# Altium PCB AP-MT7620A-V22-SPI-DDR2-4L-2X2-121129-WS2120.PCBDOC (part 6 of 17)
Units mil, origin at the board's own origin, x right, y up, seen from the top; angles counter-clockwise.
Board outline 7316 x 4279 mil, 4 copper layers (Top, Inner Layer 2, Inner Layer 3, Bottom), stack 35.4 mil thick; 640 components, 473 nets, 2041 pads, 2358 vias.
Unrouted connection lines stored in the file: 11.
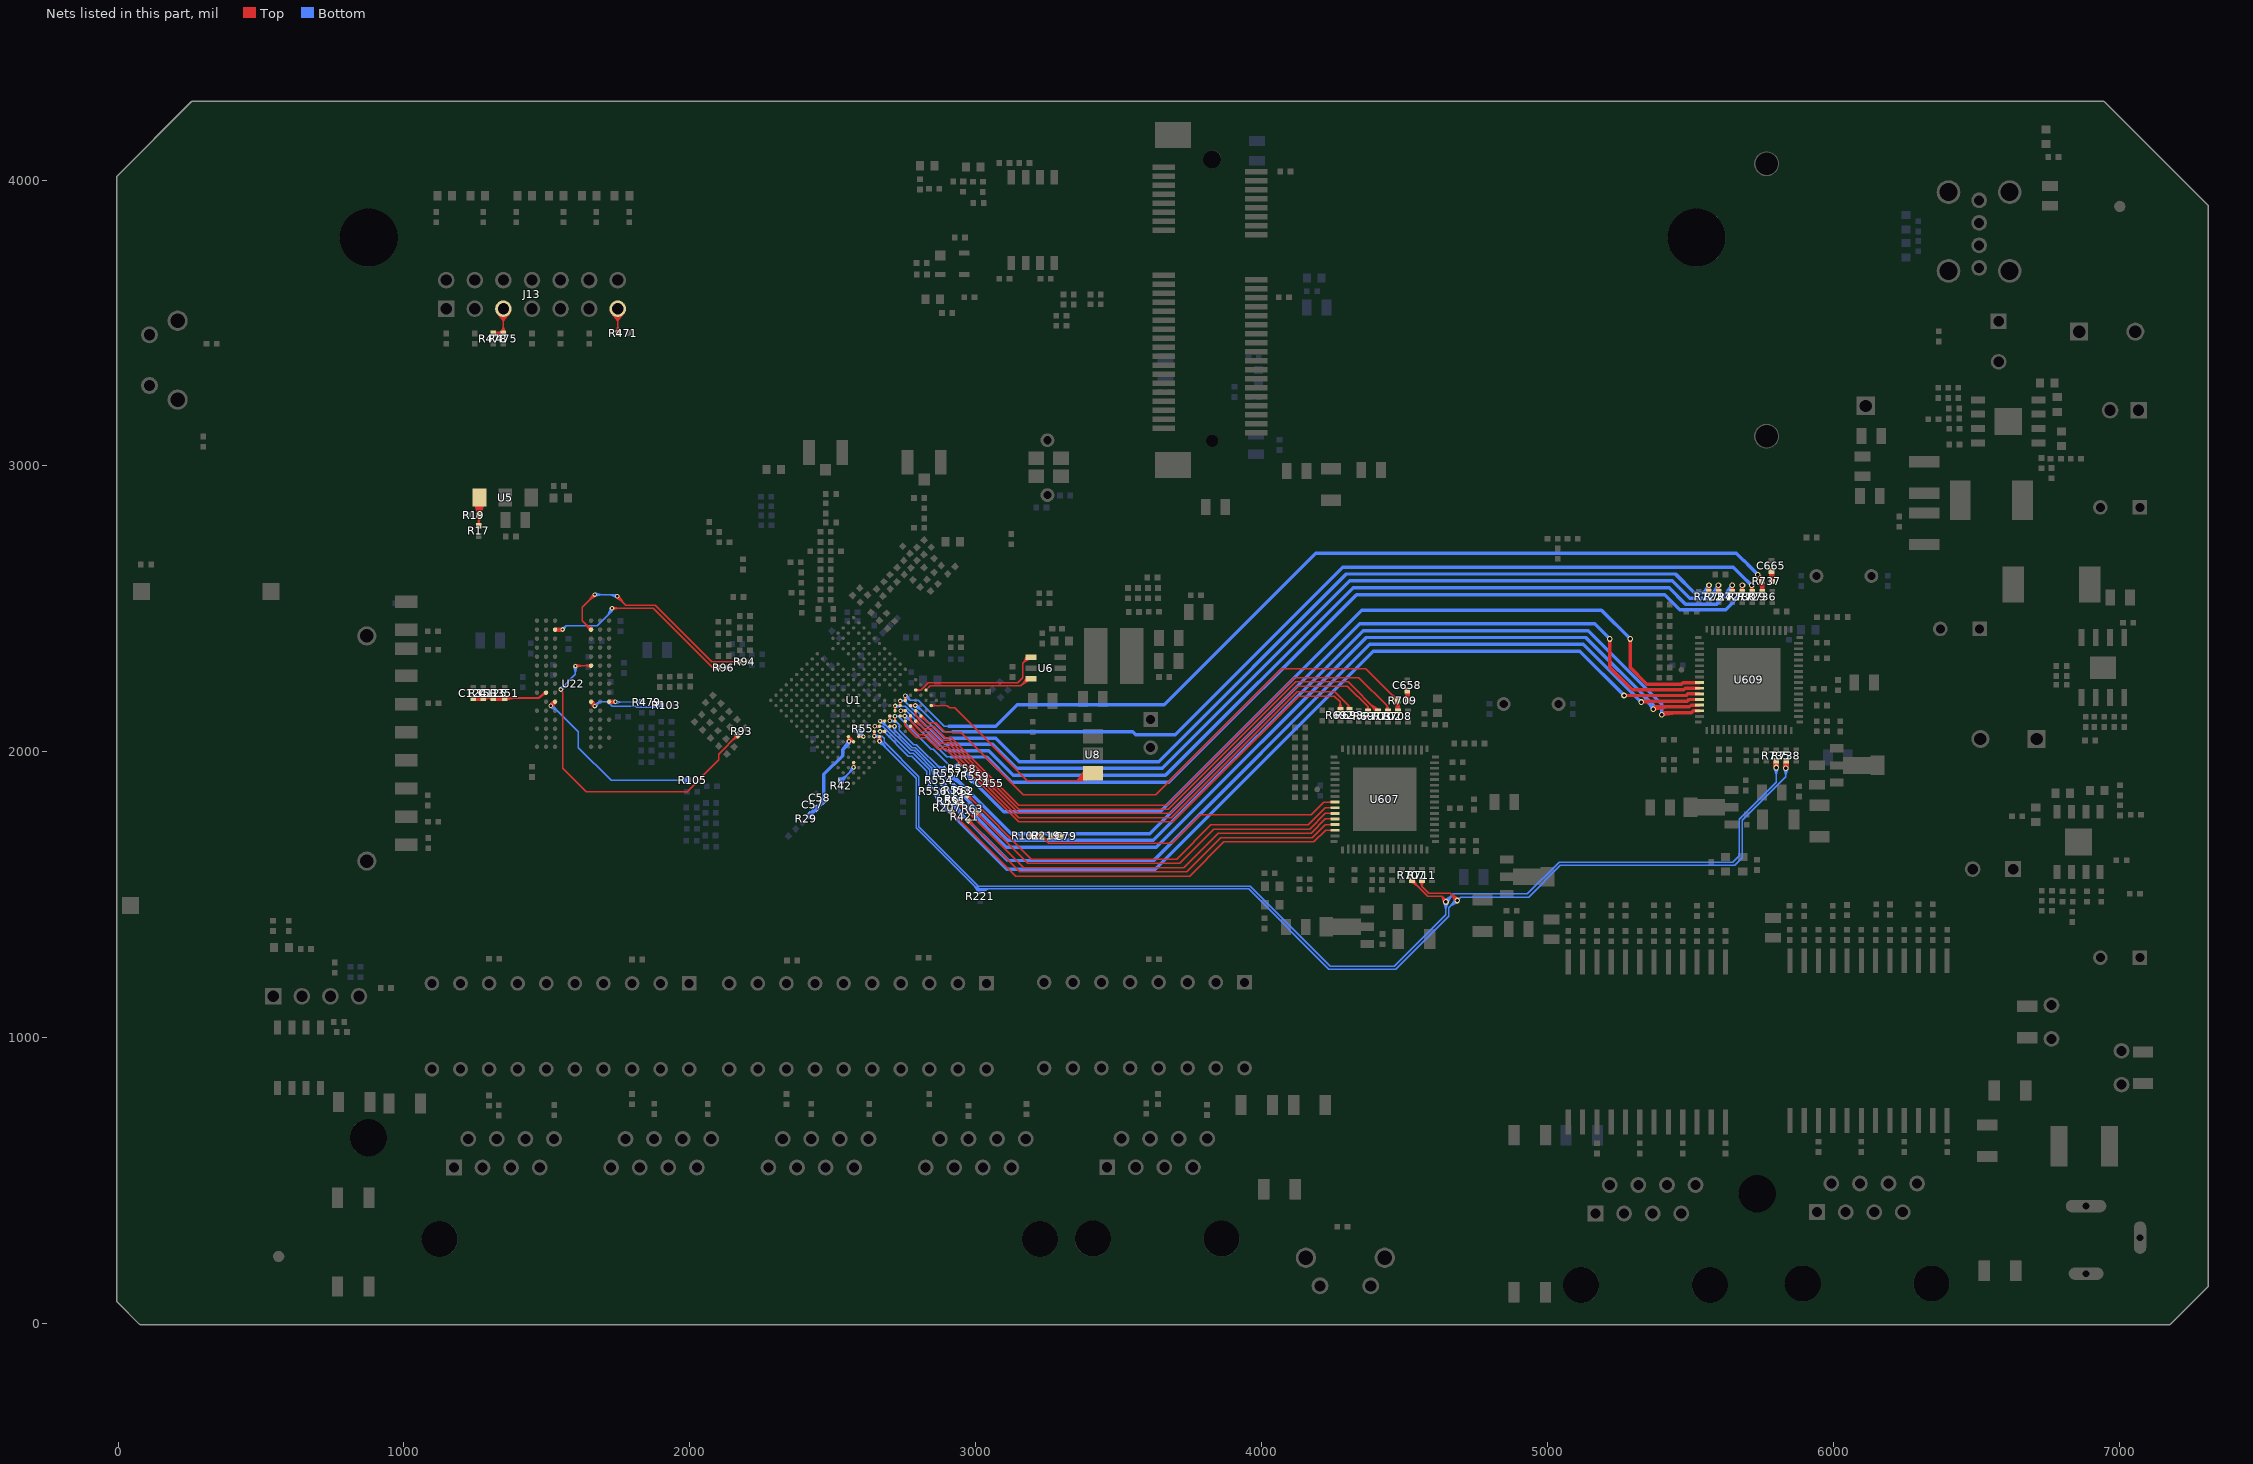
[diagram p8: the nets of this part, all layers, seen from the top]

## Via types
v1: diameter 20, hole 12, Top to Bottom, 2117 vias
v2: diameter 16, hole 8, Top to Bottom, 241 vias

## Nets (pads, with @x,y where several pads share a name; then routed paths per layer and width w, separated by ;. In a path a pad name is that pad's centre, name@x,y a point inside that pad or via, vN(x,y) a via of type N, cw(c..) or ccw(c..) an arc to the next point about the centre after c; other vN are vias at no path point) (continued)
DDR_MDQM1: R96.2 U22.B3 | length 1316
  Top w4.5: U22.B3@1529.12,2432.89 v2@1549.95,2428 ; U22.B3@1529.48,2421.75 v2@1549.95,2428 ; v2@1553,2433.39 U22.B3@1531.76,2422.44 ; v2@1553.28,2422.51 U22.B3@1531.65,2432.3 ; v2@1554.15,2433.69 U22.B3@1531.5,2427.39 ; v2@1554.3,2422.29 U22.B3@1531.5,2428 ; v2@1554.3,2433.71 U22.B3@1531.5,2428 ; v2@1554.44,2422.28 U22.B3@1531.5,2427.39 ; v2@1555.35,2433.74 U22.B3@1531.65,2432.3 ; v2@1555.66,2422.29 U22.B3@1531.76,2422.44 ; v2(1728,2502) 1873,2502 2080,2295 ; v2@1728.7,2496.29 1751.5,2502 v2@1728.7,2507.71 ; R96.2@2098.5,2287.4 2080,2295 ; R96.2@2098.5,2302.6 2080,2295 ; R96.2@2099.74,2291.76 2080,2295 ; R96.2@2099.74,2298.24 2080,2295 ; R96.2@2101,2295 R96.2@2100,2295 ; U22.B3@1531.5,2427.39 v2(1555,2428) ; U22.B3@1531.5,2428 v2(1555,2428) ; U22.B3@1531.65,2432.3 v2(1555,2428) ; U22.B3@1531.76,2422.44 v2(1555,2428) ; v2@1549.95,2428 U22.B3@1528.56,2427.3 1528.56,2428 v2(1555,2428) ; 2080,2295 R96.2@2100,2295 ; 2080,2295 R96.2@2100,2295
  Bottom w4.5: v2@1551.58,2432.63 1568.65,2441.65 ; v2(1555,2428) 1568.65,2441.65 ; v2@1559.63,2424.58 1568.65,2441.65 ; v2@1722.86,2504.59 1712.4,2477.4 ; v2@1732.53,2498.46 1712.4,2477.4 ; 1568.65,2441.65 1676.65,2441.65 1728,2493 v2(1728,2502) 1712.4,2477.4
DDR_MDQS0: R93.2 U22.F7 | length 1584.2
  Top w4.5: v2(1548.2,2218) 1556,2209 1556,1943 1638,1861 1991,1861 2102,1972 2102,1992.43 R93.2@2168.56,2058.99 ; v2@1600.38,2305.74 1623.56,2301.31 ; v2@1601.02,2294.34 1623.56,2301.31 ; U22.F7@1653.81,2295.74 1633.17,2301.31 ; U22.F7@1653.81,2306.89 1633.17,2301.31 ; R93.2@2162.25,2063.49 2151.94,2042.37 ; R93.2@2166.11,2061.12 2151.94,2042.37 ; R93.2@2169.27,2059.7 R93.2@2168.56,2058.99 ; R93.2@2170.69,2056.54 2151.94,2042.37 ; R93.2@2173.06,2052.68 2151.94,2042.37 ; 1623.56,2301.31 v2(1600,2300) 1600,2301.31 U22.F7@1654.55,2301.31 1633.17,2301.31 ; 2151.94,2042.37 R93.2@2168.56,2058.99
  Bottom w4.5: v2@1544.45,2222.35 1567.05,2238.05 ; v2@1552.78,2214.52 1567.05,2238.05 ; v2@1594.29,2299.3 1600,2276.5 ; v2@1605.71,2299.3 1600,2276.5 ; 1567.05,2238.05 v2(1548.2,2218) 1548.6,2218.4 1548.6,2219.6 1600,2271 v2(1600,2300) 1600,2276.5
DDR_MDQS1: R94.2 U22.B7 | length 1216.7
  Top w4.5: U22.B7@1650.14,2423.8 1637.13,2444.71 ; U22.B7@1658.04,2431.7 1637.13,2444.71 ; v2@1663.53,2553.62 1648.45,2530.45 ; v2@1671.62,2545.53 1648.45,2530.45 ; v2@1742.38,2539.53 1765.55,2524.45 v2@1750.47,2547.62 ; v2(1746,2544) 1776.5,2513.5 1878.5,2513.5 2077,2315 R94.2@2175,2315 ; R94.2@2173.72,2307.36 2151.5,2315 ; R94.2@2173.72,2322.64 2151.5,2315 ; R94.2@2174.78,2311.76 2151.5,2315 ; R94.2@2174.78,2318.24 2151.5,2315 ; R94.2@2176,2315 R94.2@2175,2315 ; 1637.13,2444.71 U22.B7@1654.55,2427.3 1623,2458.84 1623,2505 v2(1668,2550) 1648.45,2530.45 ; 2151.5,2315 R94.2@2175,2315
  Bottom w4.5: v2(1668,2550) 1740,2550 v2(1746,2544) 1719.92,2550 ; v2@1668.7,2544.29 1691.5,2550 v2@1668.7,2555.71 ; v2@1744.12,2538.57 1719.92,2550 ; v2@1746.68,2549.71 1719.92,2550
DDR_MODT: R479.2 U22.K9 | length 515.9
  Top w4.5: v2@1737.8,2169.69 U22.K9@1718.28,2180.9 ; v2@1737.94,2180.37 U22.K9@1718.28,2169.75 ; v2@1739.18,2169.31 U22.K9@1717.54,2175.33 ; v2@1739.35,2180.71 U22.K9@1717.54,2175.33 ; v2@1740.62,2169.28 U22.K9@1718.28,2169.75 ; v2@1740.79,2180.7 U22.K9@1718.28,2180.9 ; U22.K9@1717.54,2175.33 1739.67,2175.33 v2(1740,2175) ; U22.K9@1717.54,2175.33 v2(1740,2175) ; U22.K9@1718.28,2169.75 1738.91,2175.33 U22.K9@1718.28,2180.9 ; U22.K9@1718.28,2169.75 v2(1740,2175) ; U22.K9@1718.28,2180.9 v2(1740,2175)
  Bottom w4: v2(1740,2175) 1830,2175 1831,2176 R479.2@1833,2174 ; v2@1740.82,2169.06 1762,2175 v2@1740.82,2180.94 ; R479.2@1830.2,2166.21 1809.95,2175 ; R479.2@1830.91,2181.93 1809.95,2175 ; R479.2@1831.46,2170.04 1809.95,2175 ; R479.2@1831.82,2178 1809.95,2175 ; R479.2@1832,2174 1809.95,2175
DDR_RASN: R103.2 U22.K7 | length 705.1
  Top w4.5: v2@1662.52,2158.26 U22.K7@1659.07,2178.67 ; v2@1664.23,2155.66 U22.K7@1651.2,2170.81 ; v2@1670.38,2165.23 U22.K7@1651.2,2170.81 ; v2@1672.79,2163.18 U22.K7@1659.07,2178.67 ; U22.K7@1651.2,2170.81 v2@1668,2161.87 ; U22.K7@1651.2,2170.81 v2(1668,2160) ; U22.K7@1654.55,2175.33 v2@1668,2161.87 ; U22.K7@1654.55,2175.33 v2@1668,2161.87 ; U22.K7@1654.55,2175.33 1663.19,2156.85 U22.K7@1654.55,2175.33 ; U22.K7@1654.55,2175.33 1671.74,2164.36 U22.K7@1654.55,2175.33 ; U22.K7@1654.55,2175.33 v2(1668,2160) ; U22.K7@1654.55,2175.33 v2(1668,2160) ; U22.K7@1659.07,2178.67 v2@1668,2161.87 ; U22.K7@1659.07,2178.67 v2(1668,2160) ; v2(1668,2160) v2@1668,2161.87
  Bottom w4.5: v2@1664.48,2164.55 1684,2176 ; v2(1668,2160) 1684,2176 ; v2@1672.55,2156.48 1684,2176 ; 1728.33,2159 1711.33,2176 1684,2176
  Bottom w5: 1728.33,2159 1810.33,2159 1813.33,2156 1893,2156 R103.2@1900,2163 ; R103.2@1896.28,2169.99 1870.64,2156 ; R103.2@1899,2163 1870.64,2156 ; R103.2@1899.85,2155.55 1870.64,2156
DDR_VREF: C124.2 C125.1 R350.2 R351.1 U22.J2 | length 1615
  Top w4.5: R351.1@1353,2187 1354.1,2188 R351.1@1353,2188
  Top w8: C124.2@1242.5,2181.02 R350.2@1276.81,2181.14 ; C124.2@1242.49,2192.98 R350.2@1276.78,2192.87 ; C124.2@1243.18,2193 R350.2@1277.1,2189 ; C124.2@1243.52,2192.98 R350.2@1277.16,2187.05 ; C124.2@1243.54,2181.02 R350.2@1277.16,2187.05 ; C124.2@1243.88,2181.06 R350.2@1277.1,2189 ; C124.2@1244.54,2181.2 R350.2@1276.78,2192.87 ; C124.2@1244.54,2192.8 R350.2@1276.81,2181.14 ; R350.2@1277.12,2181.06 C124.2@1243.9,2189 ; R350.2@1277.82,2193 C124.2@1243.9,2189 ; R350.2@1278.36,2192.99 1294.7,2189 ; R350.2@1279.76,2181.27 1294.7,2189 ; C125.1@1312.6,2192.99 R351.1@1346.84,2192.29 ; C125.1@1312.68,2181.01 R351.1@1347.49,2182.17 ; C125.1@1313.18,2193 R351.1@1347.11,2189 ; C125.1@1313.47,2192.98 R351.1@1347.41,2187.33 ; C125.1@1313.58,2181.03 R351.1@1347.41,2187.33 ; C125.1@1313.88,2181.06 R351.1@1347.11,2189 ; C125.1@1314.34,2192.85 R351.1@1347.49,2182.17 ; C125.1@1314.44,2181.18 R351.1@1346.84,2192.29 ; R351.1@1352.12,2181.06 C125.1@1318.87,2189 ; R351.1@1352.82,2193 C125.1@1318.87,2189 ; R351.1@1353.35,2192.99 1387.05,2188 ; R351.1@1353.7,2181.04 1387.05,2188 ; C124.2@1243,2187 1243,2189 R350.2@1278,2189 ; C124.2@1243,2187 R350.2@1277.1,2189 ; C124.2@1243,2187 R350.2@1276.81,2181.14 ; C124.2@1243,2187 R350.2@1276.78,2192.87 ; C124.2@1243,2187 R350.2@1277.16,2187.05 ; C124.2@1243.9,2189 R350.2@1278,2187 ; R350.2@1278,2187 R350.2@1278,2189 ; R350.2@1278,2187 1294.7,2189 ; R350.2@1278,2189 1294.7,2189 ; 1294.7,2189 1353.6,2189 1354.6,2188 R351.1@1354.1,2188 ; 1294.7,2189 1313,2189 C125.1@1313,2187 ; 1294.7,2189 1311.39,2181.22 1294.7,2189 ; 1294.7,2189 1312.67,2192.99 1294.7,2189 ; 1294.7,2189 C125.1@1313,2187 ; 1294.7,2189 C125.1@1313,2187 ; C125.1@1313,2187 R351.1@1347.11,2189 ; C125.1@1313,2187 R351.1@1347.49,2182.17 ; C125.1@1313,2187 R351.1@1346.84,2192.29 ; C125.1@1313,2187 R351.1@1347.41,2187.33 ; C125.1@1318.87,2189 R351.1@1353,2187 ; R351.1@1353,2187 R351.1@1354.1,2188 ; R351.1@1353,2187 1387.05,2188 ; R351.1@1354.1,2188 1472,2188 ; 1472,2188 1491,2207 1496.89,2207 U22.J2@1497.07,2206.82 1472,2188
DDR_WEN: R105.2 U22.K3 | length 978.3
  Top w4.5: v2@1509.57,2164.84 U22.K3@1524.12,2178.78 ; v2@1510.73,2165.96 U22.K3@1528.56,2175.33 ; v2@1512.15,2166.71 U22.K3@1531.88,2170.78 ; v2@1517.5,2156.66 U22.K3@1531.88,2170.78 ; v2@1518.65,2157.79 U22.K3@1528.56,2175.33 ; v2@1519.45,2159.18 U22.K3@1524.12,2178.78 ; v2(1514.1,2161.3) U22.K3@1528.56,2175.33 ; v2(1514.1,2161.3) U22.K3@1531.88,2170.78 ; v2(1514.1,2161.3) U22.K3@1524.12,2178.78
  Bottom w4.5: v2@1511.02,2156.45 1536.04,2143.96 ; v2@1518.11,2165.42 1536.04,2143.96 ; R105.2@1990.72,1892.36 1968.5,1900 ; R105.2@1990.72,1907.64 1968.5,1900 ; R105.2@1991.78,1896.76 1968.5,1900 ; R105.2@1991.78,1903.24 1968.5,1900 ; R105.2@1992,1900 1725,1900 1610,2015 1610,2070 1520,2160 1514.1,2160 v2(1514.1,2161.3) 1536.04,2143.96
DINT_1-CPU-RT0: J13.13 R471.2 | length 636.8
  Top w4.5: J13.13@1722.61,3541.58 1748,3507.5 ; J13.13@1726.53,3544.18 1748,3507.5 ; J13.13@1730.64,3546.29 1748,3507.5 ; J13.13@1734.91,3547.93 1748,3507.5 ; J13.13@1739.3,3549.1 1748,3507.5 ; R471.2@1742.27,3465.62 1748,3488.62 ; R471.2@1746.75,3464.95 1748,3488.62 ; J13.13@1748,3550 1748,3462 1751,3465 R471.2@1750,3465 1748,3488.62 ; R471.2@1753.21,3465.5 1748,3488.62 ; J13.13@1756.7,3549.1 1748,3507.5 ; R471.2@1757.51,3466.91 1748,3488.62 ; J13.13@1761.09,3547.93 1748,3507.5 ; J13.13@1765.36,3546.29 1748,3507.5 ; J13.13@1769.47,3544.18 1748,3507.5 ; J13.13@1773.39,3541.58 1748,3507.5
EJTAG-TDO_1-CPU-RT0: J13.5 R475.2 R478.1 | length 1765.3
  Top w4.5: R478.1@1313.09,3459.75 1336.53,3462 ; R478.1@1313.36,3466.23 1336.53,3462 ; R478.1@1313.95,3455.31 1336.53,3462 ; R478.1@1314.6,3470.58 1336.53,3462 ; J13.5@1322.61,3541.58 1348,3507.5 ; J13.5@1326.53,3544.18 1348,3507.5 ; J13.5@1330.64,3546.29 1348,3507.5 ; J13.5@1334.91,3547.93 1348,3507.5 ; J13.5@1339.3,3549.1 1348,3507.5 ; R475.2@1340.36,3464.28 1348,3486.5 ; R475.2@1344.76,3463.22 1348,3486.5 ; R475.2@1345.31,3470.27 1324.41,3458.41 ; R475.2@1345.55,3455.65 1323.64,3467.04 ; R475.2@1346.03,3470.5 1324.55,3460.85 ; R475.2@1346.34,3455.43 1324.11,3464.27 ; R475.2@1346.4,3470.58 1324.47,3462 ; R475.2@1346.57,3470.62 1324.41,3462.51 ; R475.2@1346.88,3455.33 1324.41,3462.51 ; R475.2@1347.05,3455.31 1324.47,3462 ; R475.2@1347.16,3466.14 1324.41,3458.41 ; R475.2@1347.15,3470.7 1324.11,3464.27 ; R475.2@1347.26,3459.84 1323.64,3467.04 ; R475.2@1347.43,3455.27 1324.55,3460.85 ; R475.2@1347.48,3466.21 1324.55,3460.85 ; R475.2@1347.61,3459.77 1324.11,3464.27 ; R475.2@1347.64,3466.23 1324.47,3462 ; R475.2@1347.71,3466.24 1324.41,3462.51 ; R475.2@1347.84,3459.75 1324.41,3462.51 ; R475.2@1347.91,3459.75 1324.47,3462 ; R475.2@1347.95,3466.25 1324.11,3464.27 ; J13.5@1348,3550 R475.2@1348,3463 ; R475.2@1348.07,3459.75 1324.55,3460.85 ; R475.2@1348.05,3470.75 1323.64,3467.04 ; R475.2@1348.23,3455.25 1324.41,3458.41 ; R475.2@1348.32,3466.23 1323.64,3467.04 ; R475.2@1348.4,3459.77 1324.41,3458.41 ; R475.2@1351.24,3463.22 1348,3486.5 ; R475.2@1355.64,3464.28 1348,3486.5 ; J13.5@1356.7,3549.1 1348,3507.5 ; J13.5@1361.09,3547.93 1348,3507.5 ; J13.5@1365.36,3546.29 1348,3507.5 ; J13.5@1369.47,3544.18 1348,3507.5 ; J13.5@1373.39,3541.58 1348,3507.5 ; 1323.64,3467.04 R475.2@1348,3463 ; 1324.11,3464.27 R475.2@1348,3463 ; 1324.41,3458.41 R475.2@1348,3463 ; 1324.41,3462.51 R475.2@1348,3463 ; 1324.47,3462 R475.2@1348,3463 ; 1324.55,3460.85 R475.2@1348,3463 ; 1336.53,3462 R478.1@1313,3463 1313,3462 1348,3462 R475.2@1348,3463 ; 1336.53,3462 R475.2@1346.04,3455.5 ; 1336.53,3462 R475.2@1344.77,3470.04 ; 1336.53,3462 R475.2@1347.82,3459.75 ; 1336.53,3462 R475.2@1347.26,3466.17 ; 1336.53,3462 R475.2@1348,3463 ; 1336.53,3462 R475.2@1346.04,3455.5 ; 1336.53,3462 R475.2@1344.77,3470.04 ; 1336.53,3462 R475.2@1347.82,3459.75 ; 1336.53,3462 R475.2@1347.26,3466.17 ; 1336.53,3462 R475.2@1348,3463 ; 1336.53,3462 R475.2@1346.04,3455.5 ; 1336.53,3462 R475.2@1344.77,3470.04 ; 1336.53,3462 R475.2@1347.82,3459.75 ; 1336.53,3462 R475.2@1347.26,3466.17 ; 1336.53,3462 R475.2@1348,3463 ; 1336.53,3462 R475.2@1346.04,3455.5 ; 1336.53,3462 R475.2@1344.77,3470.04 ; 1336.53,3462 R475.2@1347.82,3459.75 ; 1336.53,3462 R475.2@1347.26,3466.17 ; 1336.53,3462 R475.2@1348,3463 ; 1336.53,3462 R475.2@1346.04,3455.5 ; 1336.53,3462 R475.2@1344.77,3470.04 ; 1336.53,3462 R475.2@1347.82,3459.75 ; 1336.53,3462 R475.2@1347.26,3466.17 ; 1336.53,3462 R475.2@1348,3463
EPHT_REF_RES_1-CPU-RT0: R42.2 U1.R15 | length 319.6
  Top w8: v2(2573,1946) U1.R15@2573,1962.86 v2(2573,1946)
  Bottom w4.5: R42.2@2524.51,1906.32 2548.94,1918.94 ; R42.2@2526.9,1902.48 2548.94,1918.94 ; R42.2@2531.37,1897.78 2548.94,1918.94 ; R42.2@2535.08,1895.19 2548.94,1918.94 ; v2@2568.26,1949.26 2555.19,1925.19 ; v2@2576.95,1941.82 2555.19,1925.19 ; 2548.94,1918.94 R42.2@2529,1900 2529,1899 2573,1943 v2(2573,1946) 2555.19,1925.19
EPHY_PLL_V12A_1-CPU-RT0: R55.2 U1.M13 | length 74.9
  Top w8: U1.M13@2591.1,2053.33 2607.33,2053.33 v2(2607.5,2053.5) U1.M13@2591.1,2053.33
  Bottom w8: R55.2@2593.28,2068.68 2607.5,2054.96 v2(2607.5,2053.5) R55.2@2593.28,2068.68
EPHY_V33A_1-CPU-RT0: C57.1 C58.1 R29.2 U1.N12 U1.N13 | length 1032.7
  Top w4: v2@2551.01,2037.33 U1.N12@2554.9,2053.33 ; v2@2551.07,2036.06 U1.N12@2551.72,2051.07 ; v2@2551.13,2038.26 U1.N12@2557,2051.24 ; v2@2551.25,2038.73 U1.N12@2558.81,2053.42 ; v2@2562.08,2040.19 U1.N12@2551.72,2051.07 ; v2@2562.71,2038.83 U1.N12@2554.9,2053.33 ; v2@2562.87,2038.26 U1.N12@2557,2051.24 ; v2@2562.98,2037.44 U1.N12@2558.81,2053.42 ; U1.N12@2551.72,2051.07 2557,2047 ; U1.N12@2551.72,2051.07 v2(2557,2037) ; U1.N12@2554.9,2053.33 U1.N12@2557,2051.24 ; U1.N12@2554.9,2053.33 2557,2047 ; U1.N12@2554.9,2053.33 v2(2557,2037) ; v2(2557,2037) U1.N12@2557,2051.24 ; v2(2557,2037) U1.N12@2558.81,2053.42 ; 2557,2047 U1.N12@2557,2051.24 ; 2557,2047 U1.N12@2558.81,2053.42
  Top w10: U1.N12@2554.9,2053.33 2557,2047 ; U1.N12@2554.9,2053.33 v2(2557,2037) ; U1.N12@2554.9,2053.33 2567,2037 ; U1.N12@2554.9,2053.33 2557,2047 ; U1.N12@2554.9,2053.33 U1.N13@2573,2035.24 ; U1.N12@2554.9,2053.33 v2(2557,2037) ; U1.N12@2554.9,2053.33 v2(2557,2037) ; U1.N12@2554.9,2053.33 v2(2557,2037) ; U1.N12@2554.9,2053.33 v2(2557,2037) ; U1.N12@2554.9,2053.33 v2(2557,2037) ; v2(2557,2037) 2557,2047 ; v2(2557,2037) 2567,2037 ; v2(2557,2037) U1.N13@2573,2035.24 ; v2(2557,2037) U1.N13@2571,2037 ; v2(2557,2037) U1.N13@2573,2035.24 ; v2(2557,2037) U1.N13@2573,2035.24 ; 2557,2047 2567,2037 ; 2557,2047 U1.N13@2573,2035.24 ; 2567,2037 U1.N13@2571,2037 ; U1.N13@2571,2037 2571.12,2037.12 U1.N13@2573,2035.24
  Bottom w12: 2469,1877.27 C58.1@2467.73,1827.27 2469,1828.54 2469,1921 2535,1987 2535,2007.66 ; 2535,2007.66 2557,2029.66 v2(2557,2037) 2535,2007.66
  Bottom w15: C57.1@2442.73,1801.73 R29.2@2419.02,1778.02 C57.1@2442.73,1802.27 ; C57.1@2442.73,1801.73 C57.1@2442.73,1802.27 ; C57.1@2442.73,1801.73 2419.73,1778.73 C57.1@2442.73,1802.27 ; C57.1@2442.73,1802.27 C58.1@2467.73,1827.27 C57.1@2442.73,1802.27
EXT_LDO_DIG_1-CPU-RT0: U1.B17 U8.1 | length 1986.9
  Top w4.5: U1.B17@2844.43,2161.9 2900.84,2161.9 2908.94,2153.81 2926.1,2153.81 3180.91,1899 3374,1899 ; U1.B17@2844.73,2158.26 2866.28,2161.9 U1.B17@2844.73,2165.55 ; U8.1@3384.55,1941.7 3355.15,1899 ; U8.1@3388.21,1938.93 3355.15,1899 ; U8.1@3391.59,1935.88 3355.15,1899 ; U8.1@3394.67,1932.56 3355.15,1899 ; U8.1@3397.43,1929 3355.15,1899 ; U8.1@3402.19,1920.78 3355.15,1899 ; U8.1@3403.91,1916.61 3355.15,1899 ; U8.1@3405.26,1912.29 3355.15,1899 ; U8.1@3406.23,1907.85 3355.15,1899 ; U8.1@3406.81,1903.29 3355.15,1899 ; U8.1@3410,1925 3405,1930 3374,1899 ; 3374,1899 3410.32,1904.73 3374,1899 ; 3374,1899 3379.73,1935.32 3374,1899 ; 3374,1899 3409.3,1909.3 3374,1899 ; 3374,1899 3384.3,1934.3 3374,1899 ; 3374,1899 3407.73,1913.63 3374,1899 ; 3374,1899 3388.63,1932.73 3374,1899 ; 3374,1899 3405.67,1917.69 3374,1899 ; 3374,1899 3392.69,1930.67 3374,1899 ; 3374,1899 3403.14,1921.43 3374,1899 ; 3374,1899 3396.43,1928.14 3374,1899
FB_5-POWER0: R17.2 R19.1 U5.1 | length 482.5
  Top w10: U5.1@1246.03,2878.38 R19.1@1263,2828 ; U5.1@1250.06,2866.43 R19.1@1263,2828 ; U5.1@1255.84,2880.68 R19.1@1263,2828 ; U5.1@1257.6,2867.73 R19.1@1263,2828 ; U5.1@1264.45,2881.14 R19.1@1263,2828 ; U5.1@1264.45,2889.02 1263,2887.57 R19.1@1263,2828 ; U5.1@1273.02,2880.21 R19.1@1263,2828 ; U5.1@1282.69,2877.38 R19.1@1263,2828 ; R19.1@1263,2828 1262,2827 R17.2@1262,2791 R19.1@1263,2828
G1_1-CPU-RT0: U1.B14 U6.1 | length 654.2
  Top w4.5: U1.B14@2790.51,2212.55 2808.19,2216.19 ; U1.B14@2790.51,2219.83 2808.19,2216.19 ; U6.1@3177.64,2334.59 3167.76,2312.76 ; U6.1@3181.57,2332.34 3167.76,2312.76 ; U6.1@3183.98,2330.4 3167.76,2312.76 ; U6.1@3186.11,2328.17 3167.76,2312.76 ; U6.1@3188.68,2324.44 3167.76,2312.76 ; U6.1@3193.82,2330.4 3193,2330 3191,2328 3183,2328 3165,2310 3165,2260 3146.69,2241.69 2833.69,2241.69 2808.19,2216.19 ; 2808.19,2216.19 U1.B14@2790.14,2216.19 2808.19,2216.19
G2_1-CPU-RT0: U1.A15 U6.3 | length 472.7
  Top w6: U1.A15@2826.33,2216.19 2841.57,2231.43 3158,2231.43 3181.77,2255.2 3193,2255.2 U6.3@3193.82,2255.6 ; U6.3@3178.8,2260.07 3162.13,2235.56 ; U6.3@3183.98,2255.6 3162.13,2235.56 ; U6.3@3187.99,2250.06 3162.13,2235.56
GE2_RXCLK_1-CPU-RT0: R736.1 R737.2 U1.D14 | length 3639.4
  Top w8: U1.D14@2753.95,2180 v2(2754,2196.5) U1.D14@2753.95,2180 ; U1.D14@2753.95,2180 v2(2754,2196.5) U1.D14@2753.95,2180
  Top w10: v2(2754,2196.5) v2(2754,2196.5)
  Top w15: R737.2@5749.19,2596.65 5749.19,2605.81 v1(5736,2619) R737.2@5749.19,2596.65 ; R737.2@5749.19,2596.65 5750.99,2594.85 R736.1@5750.99,2560.05 ; R737.2@5749.19,2596.65 R736.1@5750.99,2560.05 ; R737.2@5749.19,2596.65 R736.1@5750.99,2560.05
  Bottom w4.5: v2@2750.47,2191.96 2770.5,2180 ; v2(2754,2196.5) 2770.5,2180 ; v2@2758.54,2200.03 2770.5,2180 ; 2905,2090 2890,2090 2800,2180 2770.5,2180
  Bottom w12: 2905,2090 3070,2090 3145,2165 3660.3,2165 4190.3,2695 5439,2695 5660,2695 5687,2668 5688.37,2668 5736.69,2619.69 v1(5736,2619) 5699.39,2656.99
GE2_RXD0_1-CPU-RT0: R730.1 U1.F15 | length 3562.9
  Top w8: U1.F15@2735.86,2125.71 v2(2752,2125.5) U1.F15@2735.86,2125.71
  Top w12: R730.1@5680.99,2560.05 5680.99,2581.99 v1(5682,2583) R730.1@5680.99,2560.05
  Bottom w5: v2@2748.77,2121.05 2773.91,2106.2 ; v2@2756.01,2129.27 2773.91,2106.2 ; 2915,1982 2898.11,1982 2754.61,2125.5 v2(2752,2125.5) 2773.91,2106.2
  Bottom w12: 2915,1982 3038,1982 3126,1894 3676,1894 4332,2550 5410,2550 5463,2497 5623,2497 5682,2557 ; 5682,2557 v1(5682,2583) 5682,2557
GE2_RXD1_1-CPU-RT0: R727.1 U1.E15 | length 3631.9
  Top w8: U1.E15@2753.95,2143.81 2737.69,2143.81 U1.E15@2753.95,2143.81 ; U1.E15@2753.95,2143.81 v2(2737.5,2144) U1.E15@2753.95,2143.81
  Top w10: v2(2737.5,2144) v2@2737.69,2143.81
  Top w12: R727.1@5646,2560.06 v1(5646,2583) ; R727.1@5645.99,2560.05 v1(5646,2583) ; R727.1@5646,2560.06 v1(5646,2583) ; R727.1@5645.99,2560.05 v1(5646,2583)
  Bottom w4.5: v2@2738.12,2149.72 2755,2145 ; v2@2738.77,2138.39 2755,2145 ; 2905,2004 2896,2004 2755,2145 ; 2755,2145 2737.5,2145 v2(2737.5,2144) 2755,2145
  Bottom w12: 2905,2004 3046,2004 3132,1918 3664,1918 4320,2574 5426,2574 5483,2517 5593,2517 5646,2567 ; 5614.8,2537.56 v1(5646,2583) ; 5646,2567 v1(5646,2583) ; 5646,2567 v1(5646,2583) ; 5646,2567 v1(5646,2583)
GE2_RXD2_1-CPU-RT0: R724.1 U1.F14 | length 3589
  Top w4.5: v2@2717.57,2160.5 v2(2718,2160.5)
  Top w8: U1.F14@2717.76,2143.81 2717.57,2160.5 U1.F14@2717.76,2143.81 ; U1.F14@2717.76,2143.81 v2(2718,2160.5) U1.F14@2717.76,2143.81
  Top w12: R724.1@5598,2561.04 v1(5598,2583) ; R724.1@5598,2561.04 R724.1@5598.99,2560.05 v1(5598,2583) ; R724.1@5598,2561.04 v1(5598,2583)
  Bottom w4.5: v2@2718.65,2154.79 2741.5,2160.3 ; v2@2718.75,2166.2 2741.5,2160.3 ; 2900,2026 2892,2026 2792.25,2125.75 2788.25,2125.75 2753.7,2160.3 2719,2160.3 2719,2161.5 v2(2718,2160.5) 2741.5,2160.3
  Bottom w12: 2900,2026 3059,2026 3143,1942 3652,1942 4308,2598 5437,2598 5498,2537 5568,2537 5598,2567 ; 5569,2538 v1(5598,2583) ; 5598,2567 v1(5598,2583) ; 5598,2567 v1(5598,2583) ; 5598,2567 v1(5598,2583)
GE2_RXD3_1-CPU-RT0: R722.1 U1.E14 | length 3402.1
  Top w8: v2(2736,2178) 2736,2161.9 v2(2736,2178) ; v2(2736,2178) U1.E14@2735.86,2161.9 v2(2736,2178)
  Top w10: U1.E14@2735.86,2161.9 U1.E14@2736,2161.9
  Top w12: R722.1@5563.99,2560.05 5563.99,2581.99 v1(5565,2583) R722.1@5563.99,2560.05
  Bottom w5: v2(2736,2178) 2750,2178 ; v2@2737.08,2172.61 2750,2178 ; v2@2737.08,2183.39 2750,2178 ; 2910,2048 2890,2048 2793.01,2144.99 2783.01,2144.99 2750,2178
  Bottom w12: 2910,2048 3070,2048 3152,1966 3640,1966 4296,2622 5448,2622 5513,2557 5548,2557 ; 5548,2557 5565,2572 v1(5565,2583) 5548,2557
GE2_RXDV_1-CPU-RT0: R729.1 U1.D15 | length 3482.6
  Top w4.5: v2@2785.47,2161.9 v2(2788.5,2162)
  Top w8: v2@2785.47,2161.9 U1.D15@2772.05,2161.9 v2(2788.5,2162)
  Top w12: R729.1@5715,2561.04 v1(5715,2583) ; R729.1@5715,2561.04 R729.1@5715.99,2560.05 v1(5715,2583) ; R729.1@5715,2561.04 v1(5715,2583)
  Bottom w5: v2@2785.77,2157.23 2813.37,2144.61 ; v2@2792.05,2166.2 2813.37,2144.61 ; 2920,2070 2919.05,2070.95 2886.96,2070.95 2796,2162 v2(2788.5,2162) 2813.37,2144.61
  Bottom w12: 2920,2070 3550,2070 3560,2060 3698,2060 4284,2646 5649.5,2646 5712.5,2583 v1(5715,2583) 5676.47,2619.03
GE2_TXCLK_1-CPU-RT0: R558.2 U1.G15 | length 487.6
  Top w8: v2(2717.5,2124) U1.G15@2717.76,2107.62 v2@2717.76,2123.74
  Top w10: v2(2717.5,2124) v2@2717.76,2123.74
  Bottom w4.5: v2(2717.5,2124) 2730,2124 ; v2@2718.82,2118.4 2730,2124 ; v2@2718.82,2129.6 2730,2124 ; R558.2@2938.37,1960.24 2913.74,1950 ; R558.2@2939.74,1955.93 2913.74,1950 ; R558.2@2939.94,1944.99 2913.74,1950 ; R558.2@2940.27,1952.73 2913.74,1950 ; R558.2@2940.41,1949.48 2913.74,1950 ; R558.2@2940.98,1952.02 2938.96,1950 2911,1950 2852,2009 2845,2009 2730,2124
GE2_TXD0_1-CPU-RT0: R556.2 U1.J15 | length 376.4
  Top w8: U1.J15@2681.57,2071.43 2665.37,2071.43 U1.J15@2681.57,2071.43 ; U1.J15@2681.57,2071.43 v2(2665.3,2071.5) U1.J15@2681.57,2071.43
  Top w10: v2(2665.3,2071.5) v2@2665.37,2071.43
  Bottom w4.5: v2(2665.3,2071.5) 2678.5,2071.5 ; v2@2666.55,2065.89 2678.5,2071.5 ; v2@2666.55,2077.11 2678.5,2071.5 ; R556.2@2838.98,1875.02 2838.98,1874.02 R556.2@2838.27,1874.73 2838.27,1891.12 2829,1900.39 2829,1932.59 2776.59,1985 2765,1985 2678.5,2071.5
GE2_TXD1_1-CPU-RT0: R555.2 U1.J14 | length 587
  Top w8: U1.J14@2663.48,2089.52 2646.62,2089.52 U1.J14@2663.48,2089.52 ; U1.J14@2663.48,2089.52 v2(2646.5,2089.4) U1.J14@2663.48,2089.52
  Top w10: v2(2646.5,2089.4) v2@2646.62,2089.52
  Bottom w4.5: v2(2646.5,2089.4) 2675.54,2089.4 2770.04,1995 2781.11,1995 2838.69,1937.42 2838.69,1904.31 R555.2@2902.27,1840.73 ; v2@2647.2,2083.69 2670,2089.4 v2@2647.2,2095.11 ; R555.2@2895.96,1836.23 2885.66,1857.34 ; R555.2@2899.82,1838.59 2885.66,1857.34 ; R555.2@2904.41,1843.18 2885.66,1857.34 ; R555.2@2906.77,1847.04 2885.66,1857.34
GE2_TXD2_1-CPU-RT0: R554.2 U1.H14 | length 623.4
  Top w4.5: v2(2665.5,2107.6) v2@2666.8,2107.62
  Top w8: U1.H14@2681.57,2107.62 2666.8,2107.62 U1.H14@2681.57,2107.62 ; U1.H14@2681.57,2107.62 v2(2665.5,2107.6) U1.H14@2681.57,2107.62
  Bottom w4.5: v2@2662.54,2102.67 2688.7,2090.3 ; v2@2669.38,2111.85 2688.7,2090.3 ; R554.2@2853.01,1910.02 2843.84,1945.72 ; R554.2@2857.3,1911.41 2843.84,1945.72 ; R554.2@2863.11,1914.3 2843.84,1945.72 ; R554.2@2866.81,1916.89 2843.84,1945.72 ; 2688.7,2090.3 v2(2665.5,2107.6) 2665.5,2104 2675,2104 2774,2005 2784.55,2005 2860.98,1928.57 2860.98,1912.02 R554.2@2860.27,1912.73 2843.84,1945.72
GE2_TXD3_1-CPU-RT0: R553.2 U1.H15 | length 513.4
  Top w8: U1.H15@2699.67,2089.52 v2(2716,2089.5) ; U1.H15@2699.67,2089.52 v2(2716,2089.5) ; U1.H15@2699.67,2089.52 v2(2716,2089.5) ; U1.H15@2699.67,2089.52 v2(2716,2089.5)
  Bottom w4.5: v2@2710.4,2088.18 2716,2077 ; v2(2716,2089.5) 2716,2077 ; v2@2721.6,2088.18 2716,2077 ; R553.2@2918.96,1873.23 2908.66,1894.34 ; R553.2@2922.82,1875.59 2908.66,1894.34 ; R553.2@2925.27,1877.73 2908.66,1894.34 ; R553.2@2925.98,1877.02 2926.06,1876.94 2788,2015 2778,2015 2716,2077 ; R553.2@2927.41,1880.18 2908.66,1894.34 ; R553.2@2929.77,1884.04 2908.66,1894.34
GE2_TXEN_1-CPU-RT0: R557.2 U1.G14 | length 550.4
  Top w8: U1.G14@2699.67,2125.71 2699.67,2109.17 U1.G14@2699.67,2125.71 ; U1.G14@2699.67,2125.71 v2(2699.5,2109) U1.G14@2699.67,2125.71
  Top w10: v2(2699.5,2109) v2@2699.67,2109.17
  Bottom w4.5: v2@2699.39,2103.25 2721.8,2105.7 ; v2@2701.06,2114.53 2721.8,2105.7 ; R557.2@2885.48,1931.64 2865.88,1951.98 ; R557.2@2888.47,1935.02 2865.88,1951.98 ; R557.2@2891.75,1940.62 2865.88,1951.98 ; R557.2@2893.23,1944.89 2865.88,1951.98 ; 2721.8,2105.7 2704.5,2105.7 v2(2699.5,2109) 2721.8,2105.7 ; 2721.8,2105.7 2732,2095.5 2732,2076 2783,2025 2792.86,2025 2880.84,1937.02 2890.98,1937.02 R557.2@2890.27,1937.73 2865.88,1951.98
GE_2_RC_RT6352_1-CPU-RT0: C455.2 R559.1 | length 142.4
  Bottom w12: R559.1@3010.02,1927.02 R559.1@3010.73,1927.73 ; R559.1@3010.02,1927.02 C455.2@3032.04,1905 ; R559.1@3010.02,1927.02 C455.2@3037.27,1902.73 ; R559.1@3010.73,1927.73 C455.2@3032.04,1905 ; R559.1@3010.73,1927.73 C455.2@3037.27,1902.73 ; C455.2@3032.04,1905 3035,1905 C455.2@3037.27,1902.73
GE_2_TXCLK_1-CPU-RT0: R558.1 R559.2 U609.57 | length 3306.4
  Top w12: 5290,2347 v1(5290,2395) 5290,2295 5348,2237 5469,2237 5474.21,2242.21 U609.57@5531.76,2242.21 ; 5480.01,2242.21 U609.57@5520.93,2242.21
  Bottom w12: R558.1@2965.02,1927.98 R558.1@2965.73,1927.27 ; 3018.54,1870.42 R559.2@2985.27,1902.27 R558.1@2965.73,1927.27 ; 5252.54,2432.46 v1(5290,2395) 5189,2496 4351,2496 3645,1790 3098.96,1790 2985.98,1902.98 2985.98,1907.02 R558.1@2965.73,1927.27
GE_2_TXD0_1-CPU-RT0: R556.1 U609.59 | length 3348.9
  Top w12: v1(5268,2197) 5485,2197 5490.84,2202.84 ; U609.59@5520.93,2202.84 5490.84,2202.84 ; U609.59@5531.76,2202.84 5490.84,2202.84
  Bottom w12: 2896.49,1801.51 R556.1@2863.73,1849.27 ; 5230.54,2234.46 v1(5268,2197) 5113,2352 4390,2352 3628,1590 3108,1590 2867,1831 ; R556.1@2863.73,1849.27 2863.02,1849.98 2867,1849.98 2867,1831 ; R556.1@2863.73,1849.27 2867,1831 ; R556.1@2863.73,1849.27 2867,1831
GE_2_TXD1_1-CPU-RT0: R555.1 U609.60 | length 3274.9
  Top w12: 5376.32,2177 v1(5328,2174) 5328,2177 5489,2177 5495.15,2183.15 ; U609.60@5520.93,2183.15 5495.15,2183.15 ; U609.60@5531.76,2183.15 5495.15,2183.15
  Bottom w12: R555.1@2927.02,1815.98 R555.1@2927.73,1815.27 ; 2960.27,1772.73 R555.1@2927.73,1815.27 ; 5290.54,2211.46 v1(5328,2174) 5126,2376 4379,2376 3623,1620 3113,1620 2930,1803 2930,1813 R555.1@2927.73,1815.27
GE_2_TXD2_1-CPU-RT0: R554.1 U609.61 | length 3307.8
  Top w12: 5422.27,2157 v1(5370,2149) 5378,2157 5496,2157 5502.47,2163.47 ; U609.61@5520.93,2163.47 5502.47,2163.47 ; U609.61@5531.76,2163.47 5502.47,2163.47
  Bottom w12: R554.1@2885.73,1887.27 2885.02,1887.98 2898.12,1875 2964.12,1809 2964.55,1809 3107.31,1666.23 3632.23,1666.23 4366,2400 5134,2400 5370,2164 ; 5336.29,2197.71 v1(5370,2149) ; v1(5370,2149) 5370,2164 ; v1(5370,2149) 5370,2164
GE_2_TXD3_1-CPU-RT0: R553.1 U609.62 | length 3163.6
  Top w12: 5450.96,2137 v1(5400,2130) 5407,2137 5504,2137 5510,2143 ; U609.62@5520.93,2143.78 5510,2143 ; U609.62@5531.76,2143.78 5510,2143
  Bottom w12: R553.1@2950.02,1852.98 R553.1@2950.73,1852.27 3112.54,1690.46 3621.46,1690.46 4355,2424 5142,2424 5400,2166 v1(5400,2130)
GE_2_TXEN_1-CPU-RT0: R557.1 U609.58 | length 3351.4
  Top w12: 5218,2347 v1(5218,2395) 5218,2295 5297,2217 5476.48,2217 5482,2222.52 ; U609.58@5520.93,2222.52 5482,2222.52 ; U609.58@5531.76,2222.52 5482,2222.52
  Bottom w12: 2956.05,1881.95 R557.1@2915.73,1912.27 2915.02,1912.98 2925.02,1912.98 3124.74,1713.26 3608.26,1713.26 4343,2448 5165,2448 v1(5218,2395) 5180.54,2432.46
GE_MDC_1-CPU-RT0: R707.2 R735.2 U1.K14 | length 5790.3
  Top w4.5: R707.2@4521.18,1544.97 4544.97,1531.08 ; R707.2@4523.77,1548.68 4544.97,1531.08 ; R707.2@4528.47,1553.15 4544.97,1531.08 ; R707.2@4532.3,1555.55 4544.97,1531.08 ; v1@4638.15,1471.37 4630,1495 ; v1@4642.28,1473.22 4630,1495 ; v1@4647.47,1477.12 4630,1495 ; v1@4650.4,1480.55 4630,1495 ; v1@5792.25,1945.2 R735.2@5796.75,1968.83 ; v1@5792.35,1943.75 R735.2@5792.35,1967.77 ; v1@5792.59,1947.27 R735.2@5803.23,1968.83 ; v1@5793.15,1948.62 R735.2@5807.63,1967.77 ; v1@5796.76,1944.78 R735.2@5796.75,1968.83 ; v1@5796.82,1945.65 R735.2@5803.23,1968.83 ; v1@5796.86,1944.18 R735.2@5792.35,1967.77 ; v1@5797,1946.24 R735.2@5807.63,1967.77 ; v1@5803,1946.24 R735.2@5792.35,1967.77 ; v1@5803.14,1944.18 R735.2@5807.63,1967.77 ; v1@5803.18,1945.66 R735.2@5796.75,1968.83 ; v1@5803.24,1944.78 R735.2@5803.23,1968.83 ; v1@5806.85,1948.62 R735.2@5792.35,1967.77 ; v1@5807.41,1947.27 R735.2@5796.75,1968.83 ; v1@5807.65,1943.75 R735.2@5807.63,1967.77 ; v1@5807.75,1945.21 R735.2@5803.23,1968.83 ; 4544.97,1531.08 R707.2@4525.99,1551.05 4525.99,1552.05 4531.05,1546.99 4531.05,1545 4581.05,1495 4630,1495 ; 4630,1495 4645,1480 v1(4645,1475) 4630,1495 ; R735.2@5792.35,1967.77 v1@5799.99,1945.55 ; R735.2@5792.35,1967.77 v1(5800,1945) ; R735.2@5796.75,1968.83 v1@5799.99,1945.55 ; R735.2@5796.75,1968.83 v1(5800,1945) ; v1(5800,1945) R735.2@5799.99,1969.05 ; v1(5800,1945) R735.2@5799.99,1969.05 ; v1(5800,1945) R735.2@5807.63,1967.77 ; v1(5800,1945) R735.2@5803.23,1968.83 ; v1(5800,1945) R735.2@5799.99,1969.05 ; v1@5799.99,1945.55 R735.2@5807.63,1967.77 ; v1@5799.99,1945.55 R735.2@5803.23,1968.83 ; v1@5799.99,1945.55 R735.2@5799.99,1969.05 ; R735.2@5799.99,1969.05 5792.35,1946.25 R735.2@5799.99,1969.05 ; R735.2@5799.99,1969.05 5807.65,1946.25 R735.2@5799.99,1969.05 ; R735.2@5799.99,1969.05 5796.76,1945.22 R735.2@5799.99,1969.05 ; R735.2@5799.99,1969.05 5803.24,1945.22 R735.2@5799.99,1969.05
  Top w8: v2(2645.4,2055.2) U1.K14@2645.38,2071.43 ; v2(2645.4,2055.2) U1.K14@2645.38,2071.43 ; v2(2645.4,2055.2) U1.K14@2645.38,2071.43 ; v2(2645.4,2055.2) U1.K14@2645.38,2071.43
  Bottom w4.5: v2(2645.4,2055.2) 2672.2,2055.2 2680,2047.4 2680,2034.89 2801.67,1913.22 2801.67,1738.33 3009.75,1530.25 3029.75,1530.25 3030,1530 3960,1530 4240,1250 4465,1250 4645,1430 v1(4645,1475) ; v2@2646.1,2049.49 2668.9,2055.2 v2@2646.1,2060.91 ; v1@4637.34,1473.82 4645,1449.5 ; v1@4639.9,1480.84 4664.69,1497.33 ; v1@4641.76,1474.79 4645,1449.5 ; v1@4642.68,1477.28 4664.69,1497.33 ; v1@4647.55,1472.99 4664.69,1497.33 ; v1@4648.24,1474.79 4645,1449.5 ; v1@4651.43,1470.67 4664.69,1497.33 ; v1@4652.66,1473.82 4645,1449.5 ; v1@5792.34,1943.82 5800,1919.5 ; v1@5796.76,1944.79 5800,1919.5 ; v1@5803.24,1944.79 5800,1919.5 ; v1@5807.66,1943.82 5800,1919.5 ; v1(4645,1475) 4645.13,1477.77 4670.37,1503 4930,1503 5040.62,1613.62 5647.82,1613.62 5671,1636.8 5671,1765 5800,1894 v1(5800,1945) 5800,1919.5 ; v1(4645,1475) 4664.69,1497.33
GE_MDIO_1-CPU-RT0: R221.2 R711.2 R738.2 U1.K15 | length 6244
  Top w4.5: v2@2657.86,2036.59 U1.K15@2659.84,2052.92 ; v2@2658.29,2039.1 U1.K15@2667.11,2052.92 ; v2@2668.88,2039.17 U1.K15@2659.84,2052.92 ; v2@2669.35,2036.67 U1.K15@2667.11,2052.92 ; R711.2@4553.36,1549.69 4560.99,1529 ; R711.2@4557.75,1550.81 4560.99,1529 ; R711.2@4560.99,1551.05 4560.99,1529 ; R711.2@4564.23,1550.81 4560.99,1529 ; R711.2@4568.62,1549.69 4560.99,1529 ; v1@4678.87,1475.26 4663.45,1501.55 ; v1@4682.58,1477.83 4663.45,1501.55 ; v1@4687.17,1482.42 4663.45,1501.55 ; v1@4689.74,1486.13 4663.45,1501.55 ; v1@5826.27,1943.51 R738.2@5831.79,1968.5 ; v1@5826.3,1942.14 R738.2@5827.35,1967.77 ; v1@5826.63,1945.4 R738.2@5838.16,1968.33 ; v1@5827.14,1946.6 R738.2@5842.63,1967.75 ; v1@5830.75,1942.93 R738.2@5831.79,1968.5 ; v1@5830.81,1942.36 R738.2@5827.35,1967.77 ; v1@5830.83,1943.73 R738.2@5838.16,1968.33 ; v1@5831,1944.26 R738.2@5842.63,1967.75 ; R738.2@5831.75,1968.83 v1@5834.99,1945.55 ; R738.2@5834.99,1970.05 R738.2@5834.99,1969.05 ; v1@5837.08,1944.04 R738.2@5827.35,1967.77 ; v1@5837.13,1942.12 R738.2@5842.63,1967.75 ; v1@5837.21,1943.49 R738.2@5831.79,1968.5 ; v1@5837.23,1942.68 R738.2@5838.16,1968.33 ; R738.2@5838.23,1968.83 v1@5834.99,1945.55 ; v1@5841.1,1946.12 R738.2@5827.35,1967.77 ; v1@5841.53,1944.83 R738.2@5831.79,1968.5 ; v1@5841.61,1941.56 R738.2@5842.63,1967.75 ; v1@5841.75,1942.91 R738.2@5838.16,1968.33 ; U1.K15@2659.84,2052.92 v2@2663.48,2037.02 ; U1.K15@2659.84,2052.92 v2(2663.6,2036.9) ; v2@2663.48,2037.02 U1.K15@2663.48,2053.33 ; v2@2663.48,2037.02 v2(2663.6,2036.9) ; v2@2663.48,2037.02 U1.K15@2667.11,2052.92 ; v2@2663.48,2037.02 U1.K15@2663.48,2053.33 ; U1.K15@2663.48,2053.33 2657.93,2037.86 U1.K15@2663.48,2053.33 ; U1.K15@2663.48,2053.33 2669.25,2037.95 U1.K15@2663.48,2053.33 ; U1.K15@2663.48,2053.33 v2(2663.6,2036.9) ; U1.K15@2663.48,2053.33 v2(2663.6,2036.9) ; v2(2663.6,2036.9) U1.K15@2667.11,2052.92 ; 4560.99,1529 4584.99,1505 4660,1505 v1(4685,1480) 4663.45,1501.55 ; R738.2@5827.35,1967.77 v1@5834.99,1945.55 ; R738.2@5827.35,1967.77 v1(5834,1943) ; R738.2@5831.79,1968.5 v1(5834,1943) ; v1(5834,1943) 5834.99,1943.99 R738.2@5834.99,1969.05 ; v1(5834,1943) R738.2@5834.99,1968.51 ; v1(5834,1943) R738.2@5842.63,1967.75 ; v1(5834,1943) R738.2@5838.16,1968.33 ; v1(5834,1943) R738.2@5834.99,1968.51 ; v1@5834.99,1945.55 R738.2@5842.63,1967.77 ; v1@5834.99,1945.55 R738.2@5834.99,1969.05 ; R738.2@5834.99,1968.51 5826.39,1944.47 R738.2@5834.99,1968.51 ; R738.2@5834.99,1968.51 5841.7,1943.88 R738.2@5834.99,1968.51 ; R738.2@5834.99,1968.51 5830.77,1943.33 R738.2@5834.99,1968.51 ; R738.2@5834.99,1968.51 5837.25,1943.08 R738.2@5834.99,1968.51
  Bottom w4.5: v2@2659.92,2032.48 2682.88,2017.12 ; v2@2668.11,2040.46 2682.88,2017.12 ; R221.2@3010.19,1507.87 2994.24,1531.76 ; R221.2@3013.74,1510.66 2994.24,1531.76 ; R221.2@3014.93,1520.68 3041.77,1520.5 ; R221.2@3015.28,1516.17 3041.77,1520.5 ; R221.2@3017.1,1509.94 3041.77,1520.5 ; R221.2@3017.98,1515.58 2994.24,1531.76 ; R221.2@3019.22,1505.95 3041.77,1520.5 ; R221.2@3020.22,1519.5 2994.24,1531.76 ; v1@4679.46,1485.42 4661.87,1461.87 ; v1@4682.86,1482.44 4661.87,1461.87 ; v1@4686.86,1477.33 4661.87,1461.87 ; v1@4688.93,1473.32 4661.87,1461.87 ; v1@5826.34,1941.82 5834,1917.5 ; v1@5830.76,1942.79 5834,1917.5 ; v1@5837.24,1942.79 5834,1917.5 ; v1@5841.66,1941.82 5834,1917.5 ; 2682.88,2017.12 v2(2663.6,2036.9) 2668.35,2036.9 2668.35,2031.65 2791.92,1908.08 2791.92,1734.08 3005.5,1520.5 R221.2@3015,1520.5 ; 2994.24,1531.76 R221.2@3016,1513 ; R221.2@3015,1520.5 3016,1519.5 R221.2@3016,1513 ; R221.2@3015,1520.5 3954.5,1520.5 4235,1240 4470,1240 4655,1425 4655,1455 4685,1485 v1(4685,1480) ; R221.2@3016,1513 3041.77,1520.5 ; 4661.87,1461.87 v1(4685,1480) ; v1(4685,1480) 4697,1492 4934.32,1492 5045,1602.68 5654.66,1602.68 5682,1630.02 5682,1761 5834,1913 v1(5834,1943) 5834,1917.5
GE_RC_IP1001-2_1-CPU-RT0: C665.2 R737.1 | length 72.1
  Top w18: C665.2@5783.59,2632.35 5785.19,2630.75 R737.1@5785.19,2596.65 C665.2@5783.59,2632.35
GE_RC_IP1001_1-CPU-RT0: C658.2 R709.1 | length 72.1
  Top w15: C658.2@4509.59,2214.35 4511.19,2212.75 R709.1@4511.19,2178.65 C658.2@4509.59,2214.35
GE_RC_RT6352_1-CPU-RT0: C79.2 R219.1 | length 910.4
  Top w4: R219.1@3265,1706 3297,1706 C79.2@3298,1705 ; R219.1@3265.36,1702.02 3287,1706 ; R219.1@3265.36,1709.98 3287,1706 ; R219.1@3266.45,1698.13 3287,1706 ; R219.1@3266.45,1713.87 3287,1706 ; C79.2@3294.81,1697.66 3275.89,1710.25 ; C79.2@3295.42,1712.57 R219.1@3274.62,1701.26 ; C79.2@3295.5,1697.4 3276.05,1708.02 ; C79.2@3296.19,1697.21 3275.97,1706 ; C79.2@3296.2,1712.79 3275.02,1703.79 ; C79.2@3296.74,1701.2 3275.89,1710.25 ; C79.2@3296.91,1712.92 3275.97,1706 ; C79.2@3297.02,1697.06 3275.02,1703.79 ; C79.2@3297.04,1708.88 R219.1@3274.62,1701.26 ; C79.2@3297.1,1701.1 3276.05,1708.02 ; C79.2@3297.46,1701.04 3275.97,1706 ; C79.2@3297.44,1708.96 3275.02,1703.79 ; C79.2@3297.64,1712.99 3276.05,1708.02 ; C79.2@3297.82,1709 3275.97,1706 ; C79.2@3297.86,1701 3275.02,1703.79 ; C79.2@3297.91,1697 R219.1@3274.62,1701.26 ; C79.2@3298.18,1709 3276.05,1708.02 ; C79.2@3298.3,1701.01 R219.1@3274.62,1701.26 ; C79.2@3298.45,1712.99 3275.89,1710.25 ; C79.2@3298.58,1708.96 3275.89,1710.25 ; R219.1@3274.62,1701.26 C79.2@3298,1705 ; 3275.02,1703.79 C79.2@3298,1705 ; 3275.89,1710.25 C79.2@3298,1705 ; 3275.97,1706 C79.2@3298,1705 ; 3276.05,1708.02 C79.2@3298,1705 ; 3287,1706 C79.2@3294.44,1697.84 ; 3287,1706 C79.2@3295.79,1712.69 ; 3287,1706 C79.2@3296.92,1701.15 ; 3287,1706 C79.2@3297.63,1708.98 ; 3287,1706 C79.2@3298,1705 ; 3287,1706 C79.2@3294.44,1697.84 ; 3287,1706 C79.2@3295.79,1712.69 ; 3287,1706 C79.2@3296.92,1701.15 ; 3287,1706 C79.2@3297.63,1708.98 ; 3287,1706 C79.2@3298,1705 ; 3287,1706 C79.2@3294.44,1697.84 ; 3287,1706 C79.2@3295.79,1712.69 ; 3287,1706 C79.2@3296.92,1701.15 ; 3287,1706 C79.2@3297.63,1708.98 ; 3287,1706 C79.2@3298,1705 ; 3287,1706 C79.2@3294.44,1697.84 ; 3287,1706 C79.2@3295.79,1712.69 ; 3287,1706 C79.2@3296.92,1701.15 ; 3287,1706 C79.2@3297.63,1708.98 ; 3287,1706 C79.2@3298,1705
GE_RXCLK_1-CPU-RT0: R708.1 R709.2 U1.D17 | length 2670.4
  Top w5: U1.D17@2806.03,2123.12 2823.02,2110.93 U1.D17@2810.83,2127.92 ; U1.D17@2808.24,2125.71 2832.95,2101 2861,2101 2893,2069 2948.1,2069 3167.1,1850 3630,1850 4070,2290 4365,2290 4476.19,2178.81 R709.2@4476.19,2177.15 ; R709.2@4467.83,2177.23 4476.19,2153.62 ; R709.2@4469.12,2174.24 4455.2,2199.8 ; R708.1@4469.52,2141.43 4471.08,2168.04 ; R708.1@4469.53,2142.78 4475.65,2167.03 ; R708.1@4469.54,2142.94 4476.19,2167.07 ; R709.2@4476.19,2178.65 R709.2@4476.19,2177.15 ; R709.2@4479.93,2184.46 4455.2,2199.8 ; R709.2@4482.64,2177.82 4476.19,2153.62 ; R708.1@4484,2144.73 4471.08,2168.04 ; R708.1@4484.37,2143.41 4476.19,2167.07 ; R708.1@4484.33,2143.57 4475.65,2167.03 ; R708.1@4484.49,2142.25 4480.06,2168.13 ; 4455.2,2199.8 R709.2@4475.19,2178.65 ; R708.1@4469.74,2143.98 4480.06,2168.13 ; R708.1@4469.74,2143.98 4476.19,2153.62 ; R708.1@4469.74,2143.98 4476.19,2153.62 ; R708.1@4469.74,2143.98 4476.19,2153.62 ; 4471.08,2168.04 R708.1@4476.99,2142.05 ; R709.2@4475.19,2178.65 R709.2@4476.19,2177.15 ; R709.2@4475.19,2178.65 4476.19,2153.62 ; 4475.65,2167.03 R708.1@4476.99,2142.05 ; 4476.19,2153.62 R708.1@4483.9,2144.96 ; 4476.19,2153.62 R708.1@4476.99,2142.05 ; 4476.19,2153.62 R708.1@4483.9,2144.96 ; 4476.19,2153.62 R708.1@4476.99,2142.05 ; 4476.19,2153.62 R708.1@4483.9,2144.96 ; 4476.19,2153.62 R708.1@4476.99,2142.05 ; 4476.19,2167.07 R708.1@4476.99,2142.05 ; R709.2@4476.19,2177.15 4476.19,2141.85 4476.99,2141.05 R708.1@4476.99,2142.05 ; R708.1@4476.99,2142.05 4480.06,2168.13
GE_RXD0_1-CPU-RT0: R703.1 U1.E17 | length 2102.6
  Top w5: U1.E17@2787.94,2105.02 2804.93,2092.84 U1.E17@2792.74,2109.82 ; U1.E17@2790.14,2107.62 2817.76,2080 2845,2080 2885,2040 2910,2040 3151,1799 3674,1799 4120,2245 4303.04,2245 4406.99,2141.05 R703.1@4406.99,2142.05 4385.92,2162.12 ; R703.1@4401.16,2137.33 4385.92,2162.12 ; R703.1@4411.42,2148.1 4385.92,2162.12
GE_RXD1_1-CPU-RT0: R697.1 U1.E16 | length 2082.7
  Top w4.5: 2774.7,2105 2791.35,2088.35
  Top w5: U1.E16@2768.66,2125.39 2772.05,2107.65 ; 2774.7,2105 2772.05,2107.65 ; U1.E16@2775.44,2125.39 2772.05,2107.65 ; 2791.35,2088.35 2809.7,2070 2838,2070 2878,2030 2905,2030 3150,1785 3680,1785 4125,2230 4300,2230 4373,2157 ; R697.1@4364.87,2144.41 4373,2157 ; R697.1@4371.99,2141.05 4373,2142.06 4373,2157 ; R697.1@4371.99,2142.05 4373,2157 ; R697.1@4379.36,2143.43 4373,2157 ; 2772.05,2107.65 U1.E16@2772.05,2125.71 2772.05,2107.65
GE_RXD2_1-CPU-RT0: R693.1 U1.F17 | length 2002.9
  Top w5: U1.F17@2769.84,2086.93 2786.83,2074.74 ; U1.F17@2774.64,2091.73 2786.83,2074.74 ; R693.1@4300.52,2145.46 4303.02,2163.02 ; R693.1@4314.59,2149.58 4303.02,2163.02 ; 2786.83,2074.74 U1.F17@2772.05,2089.52 2801.57,2060 2833,2060 2873,2020 2900,2020 3151,1769 3684,1769 4125,2210 4256.04,2210 4303.02,2163.02 ; 4303.02,2163.02 4303.02,2149.98 4308,2145 R693.1@4308,2146 4303.02,2163.02
GE_RXD3_1-CPU-RT0: R692.1 U1.F16 | length 2030.7
  Top w4.5: 2756.5,2087 2774.75,2068.75
  Top w5: U1.F16@2750.57,2107.21 2754.5,2089 ; 2756.5,2087 2754.5,2089 ; U1.F16@2757.35,2107.41 2754.5,2089 ; 2774.75,2068.75 2793.5,2050 2828,2050 2868,2010 2895,2010 3150,1755 3690,1755 4130,2195 4255,2195 4275,2175 4275,2146 4276,2145 R692.1@4276,2146 4275,2171.02 ; R692.1@4268.55,2146.83 4275,2171.02 ; R692.1@4283.36,2147.42 4275,2171.02 ; 2754.5,2089 2754.5,2107.07 U1.F16@2753.95,2107.62 2754.5,2089
GE_RXDV_1-CPU-RT0: R702.1 U1.D16 | length 2156
  Top w4.5: 2790.14,2125.66 2809.8,2106
  Top w5: U1.D16@2786.75,2143.49 2790.14,2125.66 ; U1.D16@2793.53,2143.49 2790.14,2125.66 ; 2809.8,2106 2825.8,2090 2853,2090 2893,2050 2915,2050 3151,1814 3669,1814 4115,2260 4340,2260 4439,2161 ; R702.1@4434.5,2142.35 4439,2161 ; R702.1@4449.03,2144.64 4439,2161 ; 2790.14,2125.66 U1.D16@2790.14,2143.81 2790.14,2125.66 ; 4439,2161 4439,2144.04 4441.99,2141.05 R702.1@4441.99,2142.05 4439,2161
GE_TXCLK_1-CPU-RT0: R102.1 R219.2 U607.57 | length 2196.6
  Top w4: R102.1@3194.62,1709.98 3217.98,1710.2 ; R102.1@3194.64,1702.02 3217.61,1701.94 ; R102.1@3194.93,1714 3217.98,1710.2 ; R102.1@3194.98,1698 3217.61,1701.94 ; R102.1@3195.02,1702 3217.19,1704.12 ; R102.1@3195.02,1710 3217.33,1707.9 ; R102.1@3195.36,1702.02 3217,1706 ; R102.1@3195.36,1709.98 3217,1706 ; R102.1@3195.69,1702.06 3217.33,1707.9 ; R102.1@3195.69,1709.94 3217.19,1704.12 ; R102.1@3195.77,1698.04 3217.19,1704.12 ; R102.1@3195.75,1713.96 3217.33,1707.9 ; R102.1@3196.05,1702.14 3217.98,1710.2 ; R102.1@3196.05,1709.86 3217.61,1701.94 ; R102.1@3196.45,1698.13 3217,1706 ; R102.1@3196.45,1713.87 3217,1706 ; R102.1@3197.09,1698.28 3217.33,1707.9 ; R102.1@3197.09,1713.72 3217.19,1704.12 ; R102.1@3197.77,1698.49 3217.98,1710.2 ; R102.1@3197.76,1713.51 3217.61,1701.94 ; R219.2@3227.55,1698.13 3207,1706 ; R219.2@3227.55,1713.87 3207,1706 ; R219.2@3228.64,1702.02 3207,1706 ; R219.2@3228.64,1709.98 3207,1706 ; R219.2@3229,1706 R102.1@3195,1706 ; R102.1@3195,1706 3217.61,1701.94 ; R102.1@3195,1706 3207,1706 ; R102.1@3195,1706 3217.98,1710.2 ; R102.1@3195,1706 3207,1706 ; R102.1@3195,1706 3217.19,1704.12 ; R102.1@3195,1706 3207,1706 ; R102.1@3195,1706 3217.33,1707.9 ; R102.1@3195,1706 3207,1706 ; R102.1@3195.67,1702.06 3207,1706 ; R102.1@3195.67,1702.06 3207,1706 ; R102.1@3195.67,1702.06 3207,1706 ; R102.1@3195.67,1702.06 3207,1706 ; R102.1@3195.67,1709.94 3207,1706 ; R102.1@3195.67,1709.94 3207,1706 ; R102.1@3195.67,1709.94 3207,1706 ; R102.1@3195.67,1709.94 3207,1706 ; R102.1@3197.67,1698.46 3207,1706 ; R102.1@3197.67,1698.46 3207,1706 ; R102.1@3197.67,1698.46 3207,1706 ; R102.1@3197.67,1698.46 3207,1706 ; R102.1@3197.67,1713.54 3207,1706 ; R102.1@3197.67,1713.54 3207,1706 ; R102.1@3197.67,1713.54 3207,1706 ; R102.1@3197.67,1713.54 3207,1706
  Top w4.5: R219.2@3224.51,1699.68 3248.87,1687.13 ; R219.2@3226.91,1703.51 3248.87,1687.13 ; R219.2@3231.37,1708.22 3248.87,1687.13 ; R219.2@3235.08,1710.81 3248.87,1687.13 ; U607.57@4246.74,1821.54 4228.51,1824.21 ; U607.57@4246.74,1826.87 4228.51,1824.21 ; U607.57@4246.93,1824.21 4228.51,1824.21 ; U607.57@4257.76,1824.21 4217.21,1824.21 4173,1780 3785,1780 3685,1680 3256,1680 3230,1706 R219.2@3229,1706 3248.87,1687.13
GE_TXD0_1-CPU-RT0: R63.1 U607.59 | length 1496.8
  Top w5: R63.1@2998,1782.95 3020.12,1771.31 ; R63.1@3008.48,1793.44 3020.12,1771.31 ; 4227.01,1784.84 U607.59@4246.93,1784.84 ; U607.59@4257.76,1784.84 4222.84,1784.84 4168,1730 3833,1730 3713,1610 3181.44,1610 R63.1@3002.45,1788.99 3020.12,1771.31
GE_TXD1_1-CPU-RT0: R61.1 U607.60 | length 1549.4
  Top w5: R61.1@2937.89,1814.77 2960.02,1803.13 R61.1@2948.38,1825.26 ; R61.1@2942.34,1820.81 3168.15,1595 3728,1595 3848,1715 4173,1715 4223.15,1765.15 U607.60@4257.76,1765.15 ; 4227.01,1765.15 U607.60@4246.93,1765.15
GE_TXD2_1-CPU-RT0: R421.1 U607.61 | length 1521.9
  Top w5: R421.1@2969.71,1754.67 2991.84,1743.03 ; R421.1@2980.2,1765.15 2991.84,1743.03 ; 4227.01,1745.47 U607.61@4246.93,1745.47 ; U607.61@4257.76,1745.47 4223.47,1745.47 4178,1700 3858,1700 3738,1580 3154.87,1580 R421.1@2974.16,1760.71 2991.84,1743.03
GE_TXD3_1-CPU-RT0: R207.1 U607.62 | length 1602.2
  Top w5: R207.1@2909.49,1786.58 2931.39,1774.49 ; R207.1@2920.18,1796.85 2931.39,1774.49 ; 4227.01,1725.78 U607.62@4246.93,1725.78 ; U607.62@4257.76,1725.78 4223.78,1725.78 4183,1685 3868,1685 3748,1565 3140.88,1565 2913,1792.88 2913.35,1793.23 R207.1@2914.06,1792.52 2931.39,1774.49
GE_TXEN_1-CPU-RT0: R62.1 U607.58 | length 1549.2
  Top w5: R62.1@2966.18,1843.05 2988.3,1831.42 ; R62.1@2976.66,1853.54 2988.3,1831.42 ; 4227.01,1804.52 U607.58@4246.93,1804.52 ; U607.58@4257.76,1804.52 4222.52,1804.52 4163,1745 3823,1745 3703,1625 3194.72,1625 R62.1@2970.63,1849.09 2988.3,1831.42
